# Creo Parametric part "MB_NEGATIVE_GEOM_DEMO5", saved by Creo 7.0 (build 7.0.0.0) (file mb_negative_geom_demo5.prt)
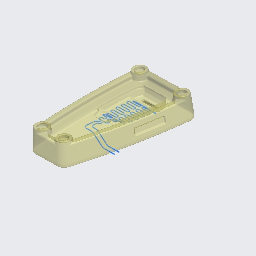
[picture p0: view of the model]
Units: millimeter Kilogram Sec (mmKs); MM, KILOGRAM, SECS

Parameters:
  COPY_GEOM_ORIGIN_TYPE = "Part"

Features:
  1. datum plane "RIGHT"
  2. datum plane "TOP"
  3. datum plane "FRONT"
  4. datum axis
  5. coordinate system
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
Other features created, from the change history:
  feature "Copy Geometry id 65689"
  curve "Copy 3"
  curve "Copied Copy 4"
  feature "Remove Body 2"
  feature "Copy Geometry id 66864"
  planar section "XSEC0002"
  protrusion "Sweep 1" (2 times)
  feature "Body Subtract 8" (2 times)
  planar section "XSEC0001" (3 times)

Other named items: SIDE_POCKET, CURVE_BODY_INTERSECT, TOP_POCKET, LOCAL_GROUP_16, LOCAL_GROUP_72, LOCAL_GROUP_58, LOCAL_GROUP_44, LOCAL_GROUP_30, LOCAL_GROUP_15, LOCAL_GROUP, LOCAL_GROUP_73, LOCAL_GROUP_59, LOCAL_GROUP_45, LOCAL_GROUP_31, LOCAL_GROUP_17, LOCAL_GROUP_1, LOCAL_GROUP_74, LOCAL_GROUP_60, LOCAL_GROUP_46, LOCAL_GROUP_32, LOCAL_GROUP_18, LOCAL_GROUP_2, LOCAL_GROUP_75, LOCAL_GROUP_61, LOCAL_GROUP_47, LOCAL_GROUP_33, LOCAL_GROUP_19, LOCAL_GROUP_3, LOCAL_GROUP_76, LOCAL_GROUP_62, LOCAL_GROUP_48, LOCAL_GROUP_34, LOCAL_GROUP_20, LOCAL_GROUP_4, LOCAL_GROUP_77, LOCAL_GROUP_63, LOCAL_GROUP_49, LOCAL_GROUP_35, LOCAL_GROUP_21, LOCAL_GROUP_5, LOCAL_GROUP_78, LOCAL_GROUP_64, LOCAL_GROUP_50, LOCAL_GROUP_36, LOCAL_GROUP_22, LOCAL_GROUP_6, LOCAL_GROUP_7, LOCAL_GROUP_79, LOCAL_GROUP_65, LOCAL_GROUP_51, LOCAL_GROUP_37, LOCAL_GROUP_23, LOCAL_GROUP_8, LOCAL_GROUP_80, LOCAL_GROUP_66, LOCAL_GROUP_52, LOCAL_GROUP_38, LOCAL_GROUP_24, LOCAL_GROUP_9, LOCAL_GROUP_81, LOCAL_GROUP_67, LOCAL_GROUP_53, LOCAL_GROUP_39, LOCAL_GROUP_25, LOCAL_GROUP_10, LOCAL_GROUP_82, LOCAL_GROUP_68, LOCAL_GROUP_54, LOCAL_GROUP_40, LOCAL_GROUP_26, LOCAL_GROUP_11, LOCAL_GROUP_83, LOCAL_GROUP_69, LOCAL_GROUP_55, LOCAL_GROUP_41, LOCAL_GROUP_27, LOCAL_GROUP_12, LOCAL_GROUP_84, LOCAL_GROUP_70, LOCAL_GROUP_56, LOCAL_GROUP_42, LOCAL_GROUP_28, LOCAL_GROUP_13, LOCAL_GROUP_85, LOCAL_GROUP_71, LOCAL_GROUP_57, LOCAL_GROUP_43, LOCAL_GROUP_29, LOCAL_GROUP_14, MAIN_BODY, COMPOSITE_PIPE_CURVE, PIPE_CURVE_BACKUP_FROZEN, MAIN, POCKET_INSERT, CURVE_BASE1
